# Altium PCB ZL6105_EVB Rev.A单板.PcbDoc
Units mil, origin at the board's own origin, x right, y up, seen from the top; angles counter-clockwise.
Board outline 787.4 x 866.14 mil, 2 copper layers (Top Layer, Bottom Layer); 7 components, 3 nets, 18 pads, 25 vias.
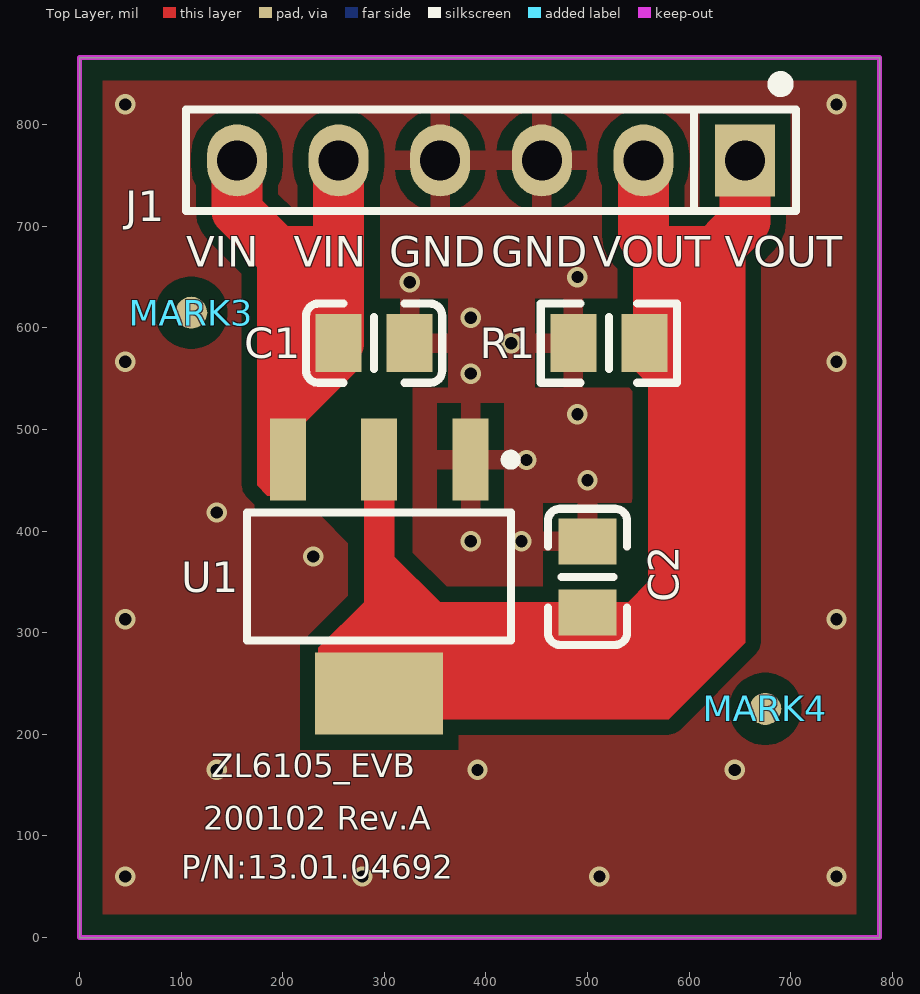
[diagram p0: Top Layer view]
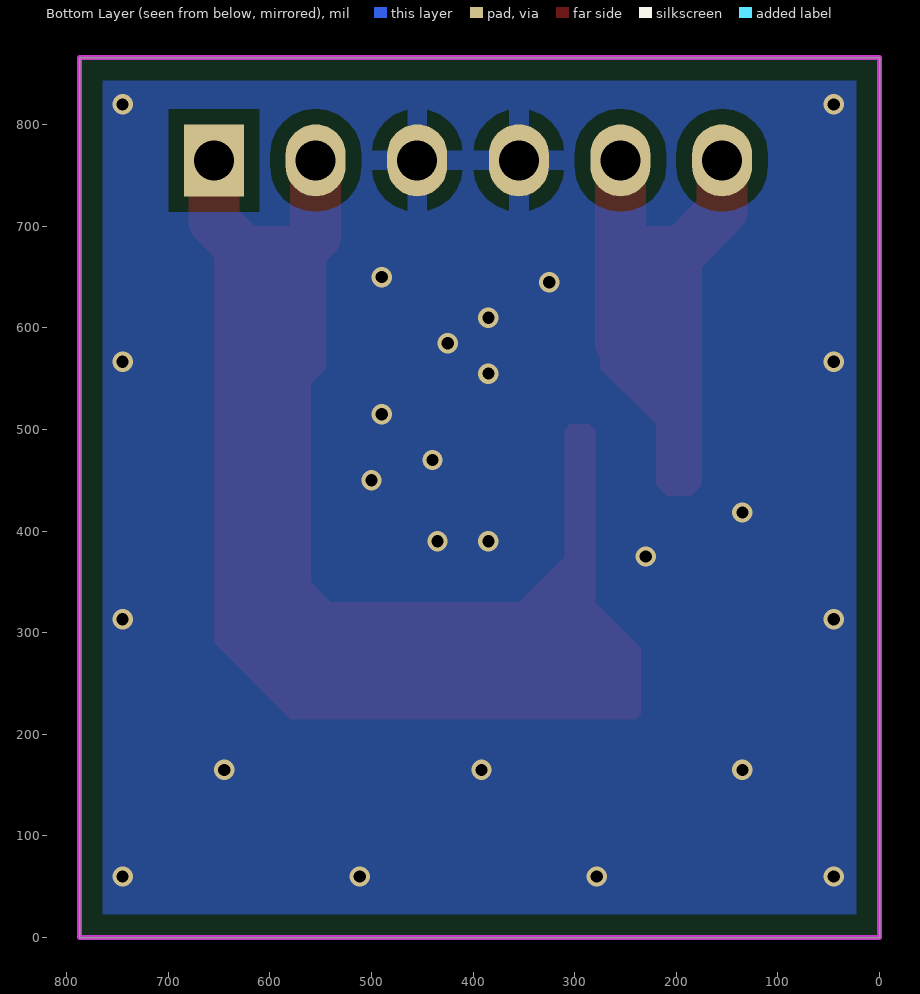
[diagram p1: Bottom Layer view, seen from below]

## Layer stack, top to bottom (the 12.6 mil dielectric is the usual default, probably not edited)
Top Layer: signal copper 1.4
Dielectric: dielectric 12.6, FR-4, Dk 4.8
Bottom Layer: signal copper 1.4

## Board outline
0,0 787.4,0 787.4,866.14 0,866.14

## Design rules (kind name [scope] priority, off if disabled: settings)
Clearance Clearance_Keepout [OnLayer('Keep-Out Layer')] p1: gap=20
Clearance Clearance_Manual [OnLayer('Bottom Layer') and IsSMTPin vs IsPadHoleValid>   (  HasFootprint('PAD-35/50') or   HasFootprint('HOLE-3.2') or  HasFootprint('HOLE-3.2 - Screw') or   HasFootprint('HOLE4.22-SMT') or   HasFootprint('Mou Hole-300D450W310H-SMD') or    HasFootprint('AW6748') or  HasFootprint('IDCS80P500W-20X2-F')  )] p2: gap=50
Clearance Clearance_Via2Via [IsVia vs IsVia] p3: gap=6
Clearance Clearance_Poly2All [InPoly] p4: gap=15
Clearance Clearance_TP [HasFootprint('PAD-40') vs HasFootprint('PAD-40')] p5: gap=50
Clearance [All] p6: gap=6
DiffPairsRouting [All] p1: maxlimit=8 minlimit=8 mostfreqgap=8 maxuncoupledlength=500
HoleSize [All] p1: absolutevalues=TRUE maxlimit=1000 minlimit=1 maxpercent=80.000 minpercent=20.000
MinimumSolderMaskSliver [All] p1: minsoldermaskwidth=4
PlaneClearance PlaneClearance_Full [IsVia] p1: clearance=9
PlaneClearance [All] p2: clearance=20
PlaneConnect PlaneConnect_Full [IsVia] p1: planeconnectstyle=Direct reliefexpansion=20 reliefentries=4 reliefconductorwidth=10 reliefairgap=10
PlaneConnect [All] p2: planeconnectstyle=Relief reliefexpansion=10 reliefentries=4 reliefconductorwidth=15 reliefairgap=10
PolygonConnect PolygonConnect_SMDHole [HasFootprint('Mou Hole-300D450W310H-SMD') or HasFootprint('Mou Hole-373D600H-SMD')] p1: connectstyle=Relief reliefconductorwidth=80 reliefentries=4 polygonreliefangle="45 Angle"
PolygonConnect PolygonConnect_Full [IsVia or   HasFootprint('PAD-40') or   HasFootprint('PAD-35/50') or  HasFootprint('HOLE-3.2') or   HasFootprint('HOLE-3.2 - Screw')] p2: connectstyle=Direct reliefconductorwidth=10 reliefentries=4 polygonreliefangle="90 Angle"
PolygonConnect [All] p3: connectstyle=Relief reliefconductorwidth=20 reliefentries=4 polygonreliefangle="90 Angle"
RoutingVias [All] p1: holewidth=12 width=20 viastyle="Through Hole" minholewidth=12 minwidth=20 maxholewidth=12 maxwidth=20
SilkToSilkClearance [All] p1: silktosilkclearance=2
SilkscreenOverComponentPads SilkToSolderMaskClearance [IsPad] p1: minsilkscreentomaskgap=2
SolderMaskExpansion [All] p1: expansion=4
Width [All] p1: maxlimit=100 minlimit=6 preferedwidth=6
21 further rules are at their usual default settings.

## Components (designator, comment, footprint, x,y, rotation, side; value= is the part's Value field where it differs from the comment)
C1 "1uF,50V,0805" 0805C 290,585 r0 top
C2 "1uF,50V,0805" 0805C 500,355 r90 top
J1 "CON6" SIP-6-2.54 405,765 r180 top
MARK3 "MARKER" MARKER-C-0.8M 110,615 r90 top
MARK4 "MARKER" MARKER-C-0.8M 675,225 r90 top
R1 "30KΩ,±5%,0805" 0805R 521,585 r0 top
U1 "ZL6105A33S2" SOT229P700X180-4N 295,355.12 r270 top

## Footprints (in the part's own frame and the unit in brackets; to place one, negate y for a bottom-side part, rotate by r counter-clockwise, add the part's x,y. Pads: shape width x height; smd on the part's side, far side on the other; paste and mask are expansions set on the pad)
0805C [mm]
  rect 1.15x1.45 smd: 1(-0.889,0) 2(0.889,0)
  silkscreen extent -1.7,-0.99 1.7,0.99, body extent -1,-0.63 1,0.63, height 0.78
0805R [mm]
  rect 1.15x1.45 smd: 1(-0.889,0) 2(0.889,0)
  silkscreen extent -1.7,-0.99 1.7,0.99, body extent -1,-0.63 1,0.63, height 0.78
MARKER-C-0.8M [mm]
  round 0.8 smd paste-1.016 mask+0.4: 0(0,0)
  Top Layer pour cut-out: -0.9,0 -0.831,-0.344 -0.636,-0.636 -0.344,-0.831 0,-0.9 0,-0.9 0.344,-0.831 0.636,-0.636 0.831,-0.344 0.9,0 0.9,0 0.831,0.344 0.636,0.636 0.344,0.831 0,0.9 0,0.9 -0.344,0.831 -0.636,0.636 -0.831,0.344 -0.9,0
SIP-6-2.54 [mm]
  rect 1.5x1.8 hole 1: 1(-6.35,0)
  oval 1.5x1.8 hole 1: 2(-3.81,0) 3(-1.27,0) 4(1.27,0) 5(3.81,0) 6(6.35,0)
  silkscreen extent -7.62,-2.03 7.62,1.27, body extent -7.62,-1.27 7.62,1.27, height 7.58
SOT229P700X180-4N [mm] "SOT223, 4-Leads, Body 6.50x7.00mm (avg), Pitch 2.29mm, IPC Medium Density"
  rect 2.05x0.9 smd: 1(-2.925,2.286) 2(-2.925,0) 3(-2.925,-2.286)
  rect 2.05x3.2 smd: 4(2.925,0)
  silkscreen extent -3.05,-3.3 1.6,3.41, body extent -3.5,-3.3 3.5,3.3, height 1.8

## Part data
C1 C2: library part 02.01.00040, "C2012X7R1H105KT000N ,0805,TDK,1uF,X7R,±10%,50V,"
J1: "Connector"
R1: library part 01.01.00305, "RTT05303JTP,0805,RALEC,30KΩ,±5%,1/8W,"
U1: "SPX1117M3-L-3-3/TR,SOTM3CU,EXAR,"

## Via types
v1: diameter 20, hole 12, Top Layer to Bottom Layer, tented both sides, 25 vias

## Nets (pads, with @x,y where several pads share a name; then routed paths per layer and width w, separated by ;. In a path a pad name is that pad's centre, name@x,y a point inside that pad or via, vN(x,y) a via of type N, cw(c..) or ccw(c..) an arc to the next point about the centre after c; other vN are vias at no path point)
GND: C1.2 C2.2 J1.3 J1.4 R1.1 U1.1
  other v1: 45,60 278.33,60 511.67,60 745,60 135,165 391.67,165 645,165 45,313.33 745,313.33 230,375 385,390 435,390 135,418.33 500,450 440,470 490,515 385,555 45,566.67 745,566.67 425,585 385,610 325,645 490,650 45,820 745,820
VIN: C1.1 J1.5 J1.6 U1.3 | length 293.6
  Top Layer w50: J1.6 155,715 200,670 ; C1.1 J1.5
VOUT: C2.1 J1.1 J1.2 R1.2 U1.2 U1.4 | length 219.9
  Top Layer w50: J1.2 555,690 575,670 ; 615,665 655,705 J1.1
pads on no net: MARK3.0 MARK4.0

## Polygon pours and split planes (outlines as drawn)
GND on Top Layer "GND_L01_P001" (solid, remove dead copper, pour order 1): 0,866.14 787.4,866.14 787.4,0 0,0 0,866.14
GND on Bottom Layer "GND_L02_P005" (solid, remove dead copper, pour order 5): 0,866.14 787.4,866.14 787.4,0 0,0 0,866.14

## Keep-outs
Keep-Out Layer:
  the board outline again, w5

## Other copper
Top Layer:
  pour cut-out: 264.71,387.93 225,427.64 225,480 290,545 325,545 327.72,542.28 327.72,357.72 325,355 280,355 265,370
  region net VOUT: 280,500 280,330 235,285 235,220 240,215 580,215 655,290 655,675 630,700 555,700 545,690 545,560 560,545 560,350 540,330 355,330 310,375 310,500 305,505 285,505
  region net VIN: 220,445 210,435 185,435 175,445 174.99,680 194.99,699.99 265,700 275,690 275,560 220,505

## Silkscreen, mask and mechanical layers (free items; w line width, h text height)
Top Overlay:
  text "VIN" at 105,660 h30
  text "VIN" at 211,660 h30
  text "GND" at 305,660 h30
  text "GND" at 405,660 h30
  text "VOUT" at 505,660 h30
  text "VOUT" at 635,660 h30
  text "ZL6105_EVB" at 129.88,150 h40
  text "200102 Rev.A" at 121.76,98.06 h40
  text "P/N:13.01.04692" at 100,50 h40
Mechanical 1:
  lines w5: 0,866.14 787.4,866.14 ; 0,866.14 0,0 787.4,0 ; 0,866.14 787.4,866.14 ; 787.4,0 787.4,866.14 ; 787.4,0 787.4,866.14
  text "F" at 330,305 h300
